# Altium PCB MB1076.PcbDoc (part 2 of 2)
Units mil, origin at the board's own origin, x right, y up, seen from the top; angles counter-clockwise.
Board outline 2200 x 4400 mil, 2 copper layers (TOP, Bottom), stack 60.433 mil thick; 144 components, 144 nets, 518 pads, 266 vias.
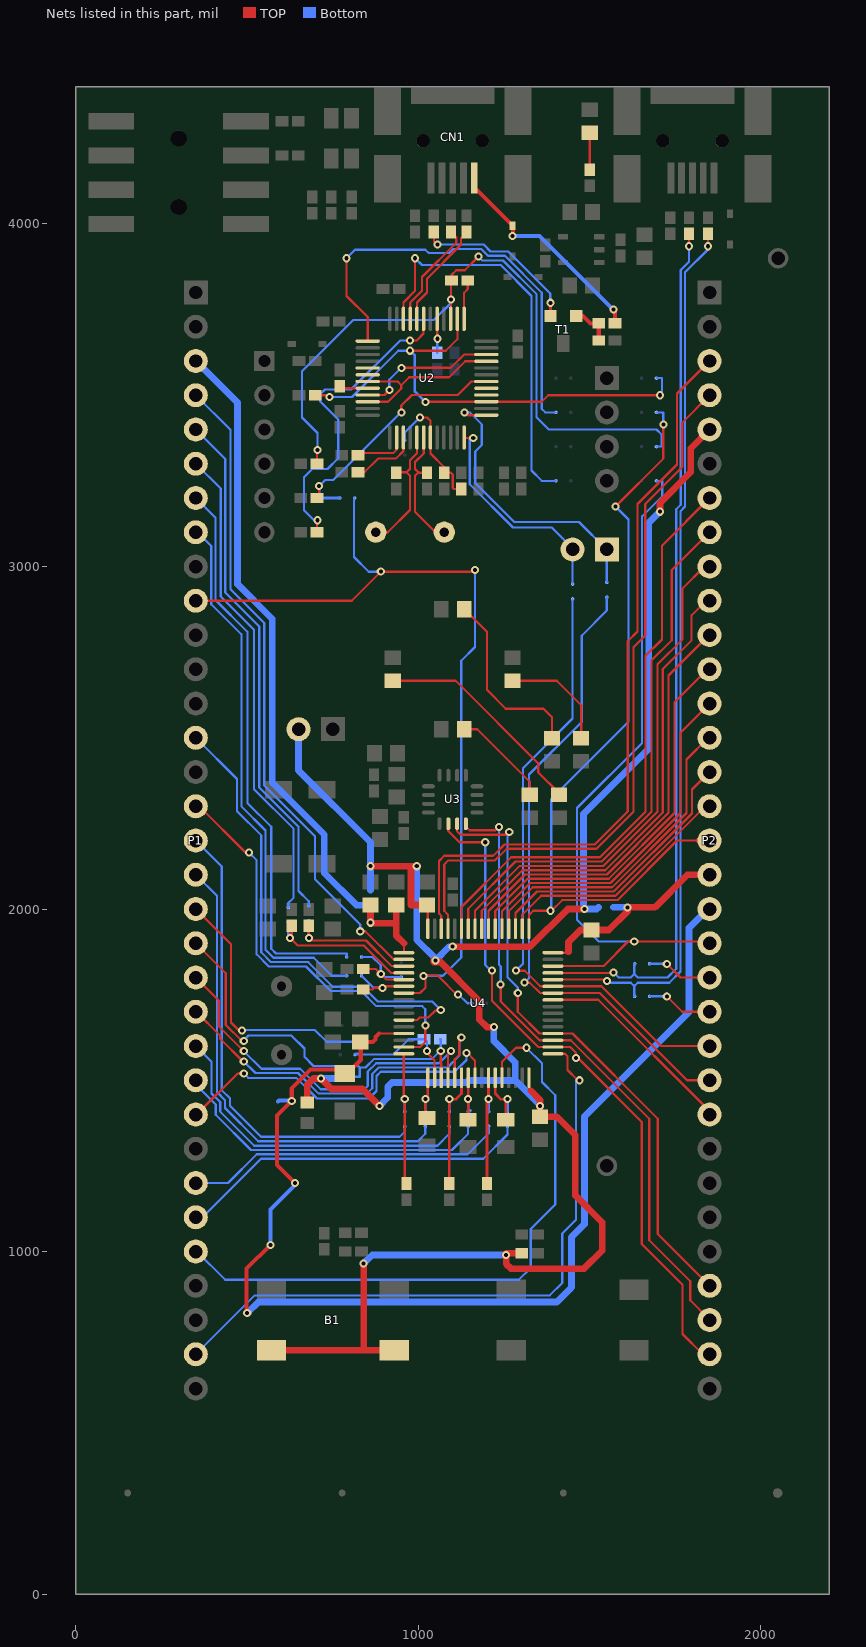
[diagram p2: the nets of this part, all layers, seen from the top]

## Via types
v1: diameter 23.62, hole 11.81, TOP to Bottom, 186 vias
v2: diameter 23.62, hole 11.81, TOP to Bottom, tented both sides, 80 vias

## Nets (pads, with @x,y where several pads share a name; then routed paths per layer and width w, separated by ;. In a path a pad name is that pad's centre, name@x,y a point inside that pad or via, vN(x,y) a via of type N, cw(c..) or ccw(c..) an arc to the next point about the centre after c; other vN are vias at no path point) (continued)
NetLD2_1: LD2.1 R3.1 | length 107.9
  TOP w6.5: R3.1@1500,4158.62 LD2.1@1500,4266.54
NetLD3_1: LD3.1 R29.2 | length 547.8
  TOP w6.5: LD3.1@1133.46,2875 1134.5,2875 1200,2809.5 1200,2640 1255,2585 1365,2585 1390,2560 R29.2@1390,2498.47
NetLD4_1: LD4.1 R32.2 | length 641.4
  TOP w6.5: LD4.1@925,2666.54 1108.46,2666.54 1350,2425 1350,2398.5 1410,2338.5 R32.2@1410,2333.47
NetLD5_1: LD5.1 R30.2 | length 326.2
  TOP w6.5: LD5.1@1275,2666.54 1403.46,2666.54 1475,2595 R30.2@1475,2498.47
NetLD6_1: LD6.1 R31.2 | length 293.2
  TOP w6.5: LD6.1@1133.46,2525 1171.5,2525 1325,2371.5 R31.2@1325,2333.47
NetR8_2: R8.2 T1.2 | length 498.1
  TOP w6.5: R8.2@1045,3976.38 1045,3948.72 1055,3938.72 v1(1055,3940)
  TOP w7.87: v1(1385,3770) 1385.33,3769.67 T1.2@1385.33,3731.34
  Bottom w6.5: v1(1055,3940) 1190.5,3940 1210.5,3920 1262,3920 1385,3797 v1(1385,3770)
NetR16_1: R16.1 R17.2 T1.1 | length 125.3
  TOP w11.81: T1.1@1460.33,3731.34 1480.16,3731.34 1502.5,3709 R16.1@1526.38,3709 ; R17.2@1526.38,3660 R16.1@1526.38,3709 ; R16.1@1526.38,3710 R16.1@1526.38,3709
NetR19_2: R19.2 U2.44 | length 84.2
  TOP w6.5: R19.2@770,3526.38 775.91,3520.47 U2.44@851.77,3520.47
NetR22_2: R22.2 U2.2 | length 158.5
  TOP w6.5: R22.2@823.62,3325 823.62,3331 926,3331 936.42,3341.42 U2.2@936.42,3376.77
NetR23_2: R23.2 U2.3 | length 197.9
  TOP w6.5: R23.2@823.62,3275 842,3275 882,3315 934,3315 956.1,3337.1 U2.3@956.1,3376.77
NetR44_1: R44.1 U2.29 | length 100.1
  TOP w6.5: U2.29@1054.53,3723.23 1054.53,3665 v1(1055,3665)
  Bottom w6.5: R44.1@1055,3623.62 v1(1055,3665)
NRST: P1.10 SB10.2 SB22.1 U4.7 | length 2685.7
  TOP w6.5: P1.10@350,2900 805,2900 v1(890,2985) 1160,2985 v1(1165,2990) ; U4.7@957.48,1754.53 1004.53,1754.53 1020.5,1770.5 1020.5,1805 v1@1020,1805 ; v1(1015,1805) v1@1020,1805 ; v1(1115,1750) 1115,1747 1056,1806 1020,1806 v1@1020,1805
  Bottom w6.5: SB10.2@813.62,3200 812,3200 812,3028 855,2985 v1(890,2985) ; v1(1015,1805) 1071.5,1805 1125,1858.5 1125,2725 1165,2765 v1(1165,2990) ; v1(1115,1750) 1118,1750 1143,1725 SB22.1@1155.32,1725
OSC_IN: C9.1 U2.5 X1.2 | length 385.6
  TOP w6.5: X1.2@875.36,3100.2 910.2,3100.2 975,3165 975,3265 965,3275 ; C9.1@935,3273.62 936.38,3275 965,3275 ; U2.5@995.47,3376.77 995.47,3330.47 975,3310 975,3285 965,3275
OSC_OUT: C10.1 U2.6 X1.1 | length 372
  TOP w6.5: U2.6@1015.16,3376.77 1015.16,3330.16 990,3305 990,3285 1001.38,3273.62 ; C10.1@1025,3273.62 1001.38,3273.62 ; X1.1@1075.36,3100.2 1049.8,3100.2 990,3160 990,3265 998.62,3273.62 1001.38,3273.62
PA1: P1.16 U4.15 | length 1240.7
  TOP w6.5: P1.16@350,2300 360,2300 495,2165 v1(505,2165) ; U4.15@957.48,1597.05 1005.55,1597.05 1020,1611.5 v1(1020,1660)
  Bottom w6.5: v1(505,2165) 527.5,2142.5 527.5,1868 563,1832.5 671.5,1832.5 743.5,1760.5 833,1760.5 877,1716.5 1011,1716.5 1020,1707.5 v1(1020,1660)
PA2: P1.17 SB27.1 | length 1385.2
  Bottom w6.5: P1.17@350,2200 426,2124 426,1471 449.5,1447.5 449.5,1425.5 540,1335 945,1335 960,1350 SB27.1@960,1365.32
PA3: P1.18 SB28.1 | length 1372.1
  Bottom w6.5: P1.18@350,2100 411.5,2038.5 411.5,1465.5 435,1442 435,1419 532,1322 998.5,1322 1020,1343.5 SB28.1@1020,1365.32
PA4: P1.21 U4.20 | length 1076.3
  TOP w6.5: P1.21@350,1800 417,1733 417,1658 v1(490,1585) ; U4.20@1086.42,1507.48 1086.42,1576.42 v1(1095,1585)
  Bottom w6.5: v1(490,1585) 541.5,1533.5 654.5,1533.5 714.5,1473.5 842.5,1473.5 852,1483 852,1525.5 876.5,1550 1060,1550 v1(1095,1585)
PA5: P1.22 U4.21 | length 1128.5
  TOP w6.5: P1.22@350,1700 350.75,1700.75 421.5,1630 421.5,1621 487.5,1555 v1(490,1555) ; U4.21@1106.1,1507.48 1106.1,1561.6 1119,1574.5 1119,1619 v1(1125,1625)
  Bottom w6.5: v1(490,1555) 524,1521 648.5,1521 708.5,1461 849,1461 865,1477 865,1518.5 884,1537.5 1084.5,1537.5 1119,1572 1119,1625 v1(1125,1625)
PA6: P1.23 SB29.1 | length 967.2
  Bottom w6.5: P1.23@350,1600 396,1554 396,1461.5 421,1436.5 421,1408.5 520.5,1309 1055.5,1309 1090,1343.5 SB29.1@1090,1365.32
PA7: P1.24 SB30.1 | length 945.5
  Bottom w6.5: P1.24@350,1500 350,1487.5 408,1429.5 408,1399.5 511,1296.5 1098,1296.5 1145,1343.5 SB30.1@1145,1365.32
PA8: P2.25 U4.41 | length 602.3
  TOP w6.5: U4.41@1392.52,1734.84 1525.16,1734.84 1849.5,1410.5 1849.5,1400 P2.25@1850,1400
PA9: P2.24 SB12.1 U4.42 | length 1882.8
  TOP w6.5: v1(1310,1785) 1325,1785 1355.47,1754.53 1529.47,1754.53 1784,1500 P2.24@1850,1500
  Bottom w6.5: v1(1310,1785) 1323,1798 1323,2392.5 1476.5,2546 1476.5,2798 1550,2871.5 SB12.1@1550,2910.32
PA10: P2.23 SB11.1 U4.43 | length 1809.8
  TOP w6.5: v1(1285,1820) 1310,1820 1355.79,1774.21 U4.43@1392.52,1774.21 1534.29,1774.21 1708.5,1600 P2.23@1850,1600
  Bottom w6.5: v1(1285,1820) 1305,1840 1305,2411 1450,2556 SB11.1@1450,2905.32
PA11: P2.22 SB23.1 | length 208.1
  TOP w6.5: v1(1725,1745) 1770,1700 P2.22@1850,1700
  Bottom w6.5: SB23.1@1674.68,1745 1715,1745 1725,1755 v1(1725,1745)
PA12: P2.21 SB20.1 | length 191.9
  TOP w6.5: v1(1725,1840) 1765,1800 P2.21@1850,1800
  Bottom w6.5: SB20.1@1674.68,1840 v1(1725,1840)
PA13: P2.20 SB9.1 U4.46 | length 2084.5
  TOP w6.5: U4.46@1392.52,1833.27 1540,1833.27 1611.73,1905 v1(1630,1905) 1845,1905 P2.20@1850,1900
  Bottom w6.5: v1(1630,1905) 1526.5,1905 1463,1968.5 1463,2295 1653,2485 1653,3146.5 1712,3205.5 1712,3250 SB9.1@1694.68,3250
PA14: P2.17 SB4.1 U4.49 | length 2301
  TOP w6.5: U4.49@1322.64,1942.52 1322.64,1982.64 1335,1995 v1(1385,1995) 1388.5,1995 1419.5,2026 1581,2026 1755,2200 P2.17@1820,2200 ; v1(1575,3175) 1715,3315 v1(1715,3415)
  TOP w19.68: P2.17@1820,2200 P2.17@1850,2200
  Bottom w6.5: v1(1385,1995) 1385,2004 1387.5,2006.5 1387.5,2321.5 1613,2547 1613,3137 v1(1575,3175) ; SB4.1@1694.68,3450 1715,3450 v1(1715,3415)
PA15: P2.16 U4.50 | length 718.8
  TOP w6.5: U4.50@1302.95,1942.52 1302.95,1982.95 1358.5,2038.5 1575.53,2038.5 1837.03,2300 P2.16@1850,2300
PB0: P1.27 SB31.1 | length 935.1
  Bottom w6.5: P1.27@350,1200 444,1200 528,1284 1143.5,1284 1205,1345.5 SB31.1@1205,1365.32
PB1: P1.28 SB32.1 | length 1033.6
  Bottom w6.5: P1.28@350,1100 369.5,1100 540.5,1271 1189,1271 1260,1342 SB32.1@1260,1365.32
PB2: P1.29 U4.28 | length 1868.3
  TOP w6.5: U4.28@1243.9,1507.48 1243.9,1553.9 1285,1595 v1(1315,1595)
  Bottom w6.5: P1.29@350,1000 353,1000 435.5,917.5 1293,917.5 1327.5,952 1327.5,1065.5 1399.5,1137.5 1399.5,1456 1360.5,1495 1360.5,1549.5 v1(1315,1595)
PB3: P2.11 U4.55 | length 1266.2
  TOP w6.5: U4.55@1204.53,1942.52 1204.53,1994.53 1311,2101 1550.31,2101 1730,2280.69 1730,2682 1848,2800 P2.11@1850,2800
PB4: P2.10 U4.56 | length 1380.5
  TOP w6.5: U4.56@1184.84,1942.52 1184.84,1994.84 1303.5,2113.5 1545.26,2113.5 1713.5,2281.74 1713.5,2701 1797.5,2785 1797.5,2857.5 1840,2900 P2.10@1850,2900
PB5: P2.9 U4.57 | length 1493
  TOP w6.5: U4.57@1165.16,1942.52 1165.16,1995.16 1296,2126 1540.22,2126 1697.5,2283.28 1697.5,2714 1770,2786.5 1770,2935 1835,3000 P2.9@1850,3000
PB6: P2.8 U4.58 | length 1596.7
  TOP w6.5: U4.58@1145.47,1942.52 1145.47,2000.47 1283.5,2138.5 1535.18,2138.5 1680,2283.32 1680,2725.5 1739.5,2785 1739.5,2989.5 P2.8@1850,3100
PB7: P2.7 U4.59 | length 1709.3
  TOP w6.5: U4.59@1125.79,1942.52 1125.79,2005.79 1271,2151 1530.13,2151 1662.5,2283.37 1662.5,2738.5 1711,2787 1711,3061 P2.7@1850,3200
PB8: P2.4 U4.61 | length 2117
  TOP w6.5: U4.61@1086.42,1942.52 1086.42,1983.58 1075,1995 1075,2130 1087,2142 1223.5,2142 1257.5,2176 1520.04,2176 1628,2283.96 1628,2764.5 1662,2798.5 1662,3182.5 1770,3290.5 1770,3420 P2.4@1850,3500
PB9: P2.3 U4.62 | length 2225.6
  TOP w6.5: U4.62@1066.73,1942.52 1066.73,1980 1060,1986.73 1060,2140 1075.5,2155.5 1218,2155.5 1251,2188.5 1515,2188.5 1611,2284.5 1611,2782 1639.5,2810.5 1639.5,3182.5 1755,3298 1755,3505 P2.3@1850,3600
PB12: P1.32 U4.33 | length 1907.4
  TOP w6.5: U4.33@1392.52,1577.36 1427.64,1577.36 1435,1570 1435,1530 1465,1500 v1(1470,1500)
  Bottom w6.5: P1.32@350,700 522,872 1383.5,872 1419.5,908 1419.5,1052.5 1460,1093 1460,1500 v1(1470,1500)
PB13: P2.32 U3.2 U4.34 | length 1980.5
  TOP w6.5: U3.2@1087.2,2249.13 1087.2,2227.8 1120,2195 v1(1195,2195) ; v1(1215,1820) 1215,1732.05 1350,1597.05 1442.95,1597.05 1460,1580 v1(1460,1565) 1465.5,1565 1652,1378.5 1652,1022 1771,903 1771,759 1830,700 P2.32@1850,700
  Bottom w6.5: v1(1195,2195) 1195,1836.5 1211.5,1820 v1(1215,1820)
PB14: P2.31 U3.4 U4.35 | length 1861.6
  TOP w6.5: U3.4@1138.39,2249.13 1138.39,2241.61 1150,2230 1225,2230 v1(1235,2240) ; v1(1240,1780) 1240,1730 1353.27,1616.73 U4.35@1392.52,1616.73 1445,1616.73 1674,1387.73 1674,1033 1793.5,913.5 1793.5,857.5 1850,801 P2.31@1850,800
  Bottom w6.5: v1(1235,2240) 1235,1837.5 1240,1832.5 v1(1240,1780)
PB15: P2.30 U3.3 U4.36 | length 1812.5
  TOP w6.5: U3.3@1112.8,2249.13 1112.8,2227.2 1123,2217 1257,2217 v1(1265,2225) ; v1(1290,1755) 1290,1700 1353.58,1636.42 1450,1636.42 1698.5,1387.92 1698.5,1051.5 P2.30@1850,900
  Bottom w6.5: v1(1265,2225) 1260,2225 1260,1801 1290,1771 v1(1290,1755)
PC3: P1.14 U4.11 | length 1421
  TOP w6.5: U4.11@957.48,1675.79 996.79,1675.79 1004,1683 1028.5,1683 1049.5,1704 1066,1704 v1(1065,1705)
  Bottom w6.5: P1.14@350,2500 470.5,2379.5 470.5,2285.5 541,2215 541,1873.5 569.5,1845 678,1845 750,1773 838.5,1773 881.5,1730 1040,1730 v1(1065,1705)
PC4: P1.25 U4.24 | length 1047.3
  TOP w6.5: P1.25@350,1400 352,1400 472,1520 v1(490,1520) ; v1(1140,1580) 1142.5,1580 1165.16,1557.34 U4.24@1165.16,1507.48
  Bottom w6.5: v1(490,1520) 503,1507 643.5,1507 704,1446.5 855,1446.5 877.5,1469 877.5,1512.5 890,1525 1105.5,1525 1140,1559.5 v1(1140,1580)
PC10: P2.15 U4.51 | length 824
  TOP w6.5: U4.51@1283.27,1942.52 1283.27,1988.27 1346,2051 1570.49,2051 1798.5,2279.01 1798.5,2349 1849.5,2400 P2.15@1850,2400
PC11: P2.14 U4.52 | length 938.6
  TOP w6.5: U4.52@1263.58,1942.52 1263.58,1993.58 1333.5,2063.5 1565.44,2063.5 1782.5,2280.56 1782.5,2436.5 1846,2500 P2.14@1850,2500
PC12: P2.13 U4.53 | length 1045.8
  TOP w6.5: U4.53@1243.9,1942.52 1243.9,1993.9 1326,2076 1560.4,2076 1765,2280.6 1765,2514.5 1850,2599.5 P2.13@1850,2600
PC13: P1.4 U4.2 | length 1925.3
  TOP w6.5: v1(830,1935) 845,1935 927.05,1852.95 U4.2@957.48,1852.95
  Bottom w6.5: P1.4@350,3500 451,3399 451,2934 550,2835 550,2360.5 698,2212.5 698,2087 830,1955 v1(830,1935)
PC14: P1.5 SB14.1 | length 1527
  Bottom w6.5: P1.5@350,3400 436,3314 436,2924 535,2825 535,2355 650,2240 650,2052.5 680,2022.5 SB14.1@680,2009.68
PC14-OSC32_IN: R35.1 SB14.2 U4.3 | length 403.2
  TOP w6.5: R35.1@680,1951.38 v1(680,1915) 680,1908 847,1908 921.73,1833.27 U4.3@957.48,1833.27
  Bottom w6.5: v1(680,1915) SB14.2@680,1966.38
PC15: P1.6 SB13.1 | length 1420
  Bottom w6.5: P1.6@350,3300 422.5,3227.5 422.5,2912.5 520,2815 520,2350 635.5,2234.5 635.5,2033 620,2017.5 SB13.1@620,2004.68
PC15-OSC32_OUT: R34.1 SB13.2 U4.4 | length 474.7
  TOP w6.5: v1(625,1915) v1@625,1916 ; R34.1@630,1951.38 630,1923.72 625,1928.72 v1@625,1916 ; U4.4@957.48,1813.58 920,1813.58 840.08,1893.5 647.5,1893.5 v1@625,1916
  Bottom w6.5: SB13.2@620,1961.38 620,1915 v1(625,1915)
PD2: P2.12 U4.54 | length 1158.9
  TOP w6.5: U4.54@1224.21,1942.52 1224.21,1994.21 1318.5,2088.5 1555.35,2088.5 1747.5,2280.65 1747.5,2603.5 1844,2700 P2.12@1850,2700
PF0: P1.7 SB17.1 | length 1643.2
  Bottom w6.5: P1.7@350,3200 407.5,3142.5 407.5,2902.5 500.5,2809.5 500.5,2309.5 570,2240 570,1884 584,1870 790.31,1870 SB17.1@790.32,1860
PF0-OSC_IN: R36.1 SB17.2 SB19.2 U4.5 | length 287.6
  TOP w6.5: R36.1@838.62,1825 875,1825 v1(890,1810) 906.1,1793.9 U4.5@957.48,1793.9
  Bottom w6.5: SB17.2@833.62,1860 866,1860 890,1836 v1(890,1810) 898.62,1801.38 SB19.2@950,1801.38
PF1: P1.8 SB18.1 | length 1574.5
  Bottom w6.5: P1.8@350,3100 355,3100 395,3060 395,2890 483,2802 483,2300 553.5,2229.5 553.5,1881 577,1857.5 694,1857.5 746.5,1805 SB18.1@790.32,1805
PF1-OSC_OUT: R37.1 SB18.2 U4.6 | length 198.5
  TOP w6.5: R37.1@838.62,1765 866.28,1765 871.28,1770 v1(895,1770) 899.21,1774.21 U4.6@957.48,1774.21
  Bottom w6.5: SB18.2@833.62,1805 868.62,1770 v1(895,1770)
STLINK_RX: JP1.1 SB12.2 U2.13 | length 870.8
  TOP w6.5: v1(1135,3450) 1143.27,3441.73 U2.13@1198.23,3441.73
  Bottom w6.5: v1(1135,3450) 1150,3450 1185,3415 1185,3354.5 1166,3335.5 1166,3244 1280,3130 1468.5,3130 1548.5,3050 JP1.1@1550,3050 SB12.2@1550,2953.62
STLINK_TX: JP1.2 SB11.2 U2.12 | length 655.6
  TOP w6.5: U2.12@1133.27,3376.77 1133.27,3375 v1(1160,3375)
  Bottom w6.5: v1(1160,3375) 1150,3375 1150,3240 1276,3114 1389.5,3114 1450,3053.5 JP1.2@1450,3050 SB11.2@1450,2948.62
STM_JTCK: SB3.2 U2.37 | length 1294.6
  TOP w6.5: v1(790,3900) 790,3790 851.77,3728.23 U2.37@851.77,3658.27
  Bottom w6.5: v1(790,3900) 815,3925 1020,3925 1030,3915 1090,3915 1102,3927 1183,3927 1203,3907 1252.5,3907 1360,3799.5 1360,3460 1370,3450 SB3.2@1401.38,3450
STM_JTMS: SB8.2 U2.34 | length 1170.2
  TOP w6.5: U2.34@956.1,3723.23 956.1,3771.1 990,3805 v1(990,3900)
  Bottom w6.5: v1(990,3900) 1010,3880 1240,3880 1330,3790 1330,3280 1360,3250 SB8.2@1401.38,3250
STM_RST: C11.2 R25.1 SB5.2 U2.7 | length 380.2
  TOP w6.5: v1(1005,3435) 1025,3435 1034.84,3425.16 U2.7@1034.84,3376.77 1034.84,3330 1075,3289.84 C11.2@1075,3273.62 1095,3273.62 1100,3268.62 1100,3230 1103.62,3226.38 R25.1@1125,3226.38
  Bottom w6.5: SB5.2@960,3368.62 960,3391.5 1003.5,3435 v1(1005,3435)
SWIM: U2.22 U2.45 | length 413
  TOP w6.5: U2.45@851.77,3500.79 900.79,3500.79 v1(915,3515) ; v1(950,3580) 1094.5,3580 1133.4,3618.9 U2.22@1198.23,3618.9
  Bottom w6.5: v1(915,3515) 915,3545 v1(950,3580)
SWIM_IN: U2.21 U2.43 U2.46 | length 503.6
  TOP w6.5: U2.46@851.77,3481.1 911.1,3481.1 950,3520 950,3529.5 ; U2.43@851.77,3540.16 939.34,3540.16 950,3529.5 ; U2.21@1198.23,3599.21 1136.21,3599.21 1089.5,3552.5 973,3552.5 950,3529.5
SWIM_RST: U2.42
SWIM_RST_IN: U2.41
T_JTCK: R20.2 SB2.1 U2.15 U2.26 | length 1481.4
  TOP w6.5: R20.2@698.62,3500 735,3500 v1(740,3495) ; v1(975,3630) 1080,3630 1113.58,3663.58 U2.26@1113.58,3723.23 ; v1(1020,3480) 1020,3481.1 U2.15@1198.23,3481.1 1360.1,3481.1 1379,3500 v1(1705,3500)
  Bottom w6.5: v1(740,3495) 806,3495 941,3630 v1(975,3630) ; SB2.1@1694.68,3550 1711,3550 1711,3500 v1(1705,3500)
  Bottom w7.87: v1(975,3630) 989.5,3615.5 989.5,3510.5 v1(1020,3480)
T_JTDI: U2.17
T_JTDO: U2.16
T_JTMS: R14.2 R21.2 SB7.1 U2.27 | length 2060.4
  TOP w6.5: R21.2@703.62,3300 703.62,3338.62 v1(705,3340) ; U2.27@1093.9,3723.23 1095,3723.23 v1(1095,3780) 1095,3835 R14.2@1096.38,3835 1096.38,3851.38 1110,3865 1135,3865 v1(1175,3905)
  Bottom w6.5: v1(705,3340) 705,3390 660,3435 660,3570 809.5,3719.5 1045,3719.5 1095,3769.5 v1(1095,3780) ; v1(1175,3905) 1186.5,3893.5 1246.5,3893.5 1345,3795 1345,3435 1380,3400 1695,3400 1710,3385 1710,3350 SB7.1@1694.68,3350
T_NRST: R24.2 SB10.1 U2.18 | length 758.1
  TOP w6.5: R24.2@703.62,3200 710,3200 v1(710,3235) ; v1(950,3450) 950,3470 981,3501 1115,3501 1154.16,3540.16 U2.18@1198.23,3540.16
  Bottom w6.5: v1(710,3235) 727.5,3252.5 751.5,3252.5 949,3450 v1(950,3450)
  Bottom w7.87: v1(710,3235) 710,3208.5 718.5,3200 SB10.1@770.32,3200
T_SWDIO_IN: R14.1 U2.25 | length 116.1
  TOP w6.5: U2.25@1133.27,3723.23 1133.27,3799.65 1143.62,3810 R14.1@1143.62,3835
T_SWO: R28.2 U2.31 | length 933.8
  TOP w6.5: R28.2@703.62,3100 703.62,3135 v1(705,3135) ; v1(975,3660) 995,3660 1015,3680 1015,3723.23 U2.31@1015.16,3723.23
  Bottom w6.5: v1(705,3135) 695,3135 665.5,3164.5 665.5,3260.5 690,3285 734.5,3285 765.5,3316 765.5,3429.5 713.5,3481.5 713.5,3503 727,3516.5 803,3516.5 946.5,3660 v1(975,3660)
TS_G1_IO3: R38.1 SB27.2 U4.16 | length 422.2
  TOP w7.87: U4.16@957.48,1577.36 957.48,1446.52 v1@960,1444 ; v1(960,1445) v1@960,1444 ; R38.1@965,1198.62 960,1198.62 v1@960,1444
  Bottom w7.87: SB27.2@960,1408.62 v1(960,1445)
TS_G1_IO4: C26.2 SB28.2 U4.17 | length 161.9
  TOP w7.87: C26.2@1025,1390 1020,1390 v1(1020,1445) 1020,1447.5 1027.36,1454.86 U4.17@1027.36,1507.48
  Bottom w7.87: SB28.2@1020,1408.62 v1(1020,1445)
TS_G2_IO3: R39.1 SB29.2 U4.22 | length 371.8
  TOP w7.87: R39.1@1090,1198.62 v1(1090,1445) 1110,1445 1125.79,1460.79 U4.22@1125.79,1507.48
  Bottom w7.87: SB29.2@1090,1408.62 v1(1090,1445)
TS_G2_IO4: C27.2 SB30.2 U4.23 | length 174.5
  TOP w7.87: C27.2@1145,1385 1145.47,1394.53 1145.47,1438.5 1145,1438.03 v1@1145,1443 ; v1(1145,1445) v1@1145,1443 ; U4.23@1145.47,1507.48 1145.47,1443.47 v1@1145,1443
  Bottom w7.87: SB30.2@1145,1408.62 1149.12,1408.62 1152,1411.5 1145,1411.5 v1(1145,1445)
TS_G3_IO2: R40.1 SB31.2 U4.26 | length 356.2
  TOP w7.87: R40.1@1200,1198.62 v1@1200,1437.97 ; U4.26@1204.53,1507.48 v1@1204.53,1444.53 ; v1(1205,1445) v1@1204.53,1444.53 ; v1@1200,1437.97 1204.53,1442.5 v1@1204.53,1444.53 ; v1@1200,1437.97 1200,1440 v1@1204.53,1444.53
  Bottom w7.87: SB31.2@1205,1408.62 v1(1205,1445)
TS_G3_IO3: C28.2 SB32.2 U4.27 | length 185.4
  TOP w7.87: U4.27@1224.21,1507.48 1224.21,1460.79 1240,1445 v1@1255,1445 ; C28.2@1255,1385 v1@1255,1445 ; v1(1260,1445) v1@1255,1445
  Bottom w7.87: SB32.2@1260,1408.62 v1(1260,1445)
U5V: CN1.1 D1.1 R16.2 | length 645.4
  TOP w11.81: CN1.1@1162.89,4134.25 1162.89,4107.11 D1.1@1275,3995 1276,3995 1276,3965 v1(1275,3965) ; v1(1570,3750) 1573.62,3750 R16.2@1573.62,3710
  Bottom w11.81: v1(1275,3965) 1353.5,3965 1568.5,3750 v1(1570,3750)
USB_DM: R10.2 U2.32 | length 313
  TOP w6.55: U2.32@995.47,3723.23 995.47,3770.47 1025,3800 1025,3840.5 1124.5,3940 1124.5,3957.5 1140,3973 R10.2@1140,3976.38
USB_DP: R9.2 U2.33 | length 315
  TOP w6.55: U2.33@975.79,3723.23 975.79,3770.79 1010,3805 1010,3845.5 1110,3945.5 1110,3961.38 R9.2@1095,3976.38
USBF4_DM: R13.2 SB23.2 U4.44 | length 2619.2
  TOP w6.55: U4.44@1392.52,1793.9 1546.1,1793.9 v1(1550,1790) ; v1(1845,3935) R13.2@1845,3971.38
  Bottom w6.55: v1(1550,1790) 1550,1785 1620,1785 1630,1775 ; SB23.2@1631.38,1745 1630,1745 1630,1775 ; v1(1845,3935) 1845,3925.5 1778.5,3859 1778.5,3175 1765,3161.5 1765,1817.5 1732.5,1785 1640,1785 1630,1775
USBF4_DP: R12.2 SB20.2 U4.45 | length 2591.6
  TOP w6.55: U4.45@1392.52,1813.58 1570,1813.58 v1(1570,1815) ; v1(1790,3935) 1798.72,3935 1794.36,3939.36 1790,3943.72 R12.2@1790,3971.38
  Bottom w6.55: v1(1570,1815) 1585,1800 1620,1800 1630,1810 ; SB20.2@1631.38,1840 1630,1840 1630,1810 ; v1(1790,3935) 1790,3890 1765.5,3865.5 1765.5,3180.5 1752.5,3167.5 1752.5,1825.5 1727,1800 1640,1800 1630,1810
VBAT: C16.1 C17.2 P1.3 SB15.2 U4.1 | length 2151.7
  TOP w6.5: C16.1@860,2010 C16.1@860,2011.53 ; U4.1@957.48,1872.64 957.48,1900
  TOP w19.68: C16.1@860,2010 v1(860,1960) 860,1958.5 935,1958.5 ; C17.2@935,2011.53 935,1958.5 ; 957.48,1900 935,1922.48 935,1958.5
  Bottom w19.68: P1.3@350,3600 471.5,3478.5 471.5,2948.5 573,2847 573,2369 725,2217 725,2105 818.62,2011.38 SB15.2@860,2011.38 v1(860,1960)
VDD: B1.1 B1.4 C18.1 C29.2 JP2.2 L1.1 P2.5 R43.2 SB15.1 SB16.1 SB25.2 U4.32 U4.64 | length 6755.5
  TOP w6.5: C18.1@1025,2011.53 1027.36,2009.17 U4.64@1027.36,1942.52 ; U4.32@1322.64,1507.48 1322.64,1475 1328.14,1469.5
  TOP w19.68: B1.4@570.87,711.42 841,711.42 ; L1.1@675,1435 675,1486.5 693.5,1505 v1(715,1505) 745.5,1474.5 836.5,1474.5 v1(886,1425) ; v1(840,965) 840,712.42 841,711.42 ; v1(860,2125) 978,2125 ; B1.1@929.13,711.42 841,711.42 ; v1(995,2125) 978,2125 ; C18.1@1025,2011.53 978,2011.54 978,2125 ; v1(1050,1850) 1045,1850 1045,1845 1064,1845 1177.5,1731.5 1177.5,1677 1199.5,1655 v1(1220,1655) ; v1(1100,1890) 1326,1890 1436,2000 v1(1485,2000) ; v1(1255,990) 1252,990 v1@1256,994 ; R43.2@1301.38,995 1256,995 v1@1256,994 ; 1328.14,1469.5 1355,1442.64 v1(1355,1425) C29.2@1355,1393.47 1404.03,1393.47 1458,1339.5 1458,1163 1536.5,1084.5 1536.5,1003 1483.5,950 1270,950 1256,964 v1@1256,994 ; v1(1705,3160) 1705,3185.5 1795,3275.5 1795,3345 P2.5@1850,3400
  Bottom w19.68: JP2.2@650,2525 650,2405 860,2195 v1(860,2125) SB15.1@860,2054.68 ; v1(715,1505) 760,1505 765.69,1510.69 SB25.2@766.38,1510 ; v1(840,965) 865,990 v1(1255,990) ; v1(886,1425) 910,1449 910,1480.5 923,1493.5 1140.5,1493.5 1146,1499 1279.5,1499 ; v1(995,2125) 995,1910 1050,1855 v1(1050,1850) 1090,1890 v1(1100,1890) ; v1(1220,1655) 1220,1614.5 1282.5,1552 1282.5,1502 1279.5,1499 ; v1(1355,1425) 1355,1427.5 1283.5,1499 1279.5,1499 ; SB16.1@1525.32,2005 1520.31,2000 v1(1485,2000) 1482,2000 1482,2278 1672.5,2468.5 1672.5,3128 1705,3160.5 v1(1705,3160)
VDD3: C33.1 P1.20 SB25.1 U4.19 | length 1163.6
  TOP w6.5: P1.20@350,1900 437.5,1812.5 437.5,1661.5 484,1615 v1(490,1615) ; v1(1065,1585) 1065,1550 1066.73,1548.27 U4.19@1066.73,1507.48
  Bottom w6.5: v1(490,1615) 490,1617 504,1631 628.5,1631 667,1592.5 667,1568.5 693.5,1542 823.5,1542 828.5,1537 ; SB25.1@809.68,1510 828.5,1510 828.5,1537 ; C33.1@1063.62,1620 1065,1620 v1@1065,1587.5 ; v1(1065,1585) v1@1065,1587.5 ; 828.5,1537 845.5,1537 871,1562.5 1040,1562.5 v1@1065,1587.5
VDD_USB: C21.2 P2.18 SB16.2 U4.48 | length 616.4
  TOP w7.87: U4.48@1392.52,1872.64 1435,1872.64 1437.86,1875.5
  TOP w19.68: 1437.86,1875.5 1438,1875.64 1438,1903.5 1472.96,1938.47 C21.2@1505,1938.47 1555.46,1938.47 1610,1993 v1(1610,2005) 1690,2005 1785,2100 P2.18@1850,2100
  Bottom w19.68: SB16.2@1568.62,2005 v1(1610,2005)
VDDA: C24.2 C25.1 P2.19 SB26.2 U4.13 | length 3510
  TOP w6.5: 885,1636.42 U4.13@957.48,1636.42
  TOP w11.81: v1(500,820) 505.5,820 498.5,827 498.5,950 v1(568,1019.5) ; v1(640,1200) 640,1200.5 587.5,1253 587.5,1397.5 v1(630,1440) 630,1476 685,1531 785,1531 C25.1@785,1520 792,1520 831.5,1559.5 C24.2@831.5,1611.54 ; C24.2@831,1611.54 C24.2@831.5,1611.54 ; 885,1636.42 884.42,1636.42 874.5,1626.5 874.5,1619.54 866.5,1611.54 C24.2@831.5,1611.54
  TOP w19.68: C24.2@830,1611.53 C24.2@831,1611.54
  Bottom w11.81: v1(568,1019.5) 568,1123 645,1200 v1(640,1200) ; SB26.2@590,1438.62 592.88,1441.5 630,1441.5 v1(630,1440)
  Bottom w19.68: v1(500,820) 533,853 1404,853 1446.5,895.5 1446.5,1042 1484.5,1080 1484.5,1394 1790,1699.5 1790,1945 1845,2000 P2.19@1850,2000
VSS3: C33.2 P1.19 SB24.1 U4.18 | length 1185.5
  TOP w6.5: P1.19@350,2000 452.5,1897.5 452.5,1669 479,1642.5 485,1642.5 v1(485,1645) ; v1(1025,1585) 1020.5,1585 1047.05,1558.45 U4.18@1047.05,1507.48
  Bottom w6.5: v1(485,1645) 487,1647 697.5,1647 732,1612.5 821.5,1612.5 834.5,1599.5 834.5,1577.5 817.18,1577.5 SB24.1@814.68,1575 926.5,1575 971.5,1620 C33.2@1016.38,1620 1018.5,1620 1025,1613.5 v1(1025,1585)
pads on no net: CN1.11 CN1.12 CN2.11 CN2.12 CN3.2 CN3.6 CN3.9 CN3.10 U2.4 U2.11 U2.14 U2.19 U2.28 U2.38 U2.39 U2.40 X2.2 X2.3

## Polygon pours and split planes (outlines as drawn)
GND on Bottom "BOTTOM_GND_P015" (hatched 90Degree grid 62.99 track 7.87, remove dead copper, pour order 15): -395,-305 2700,-305 2700,800 -395,800
GND on Bottom "BOTTOM_GND_P016" (solid, remove dead copper, pour order 16): -400,787 2695,787 2695,4470 -400,4470
GND on TOP "TOP_GND_P013" (hatched 90Degree grid 62.99 track 7.87, remove dead copper, pour order 13): 975,650 -449.43,650 -449.43,-465 2430,-465 2430,650 1225,650 1225,595 1472.86,595 1512.86,560 2105,560 cw(c2105,510) 2155,510 2155,85 cw(c2105,85) 2105,35 95,35 cw(c95,85) 45,85 45,510 cw(c95,510) 95,560 685,560 726.45,600 975,600
GND on TOP "TOP_GND_P014" (solid, remove dead copper, pour order 14): -422.93,600 975,600 975,975 900,1050 900,1585 995,1585 1016.5,1563.5 1301,1563.5 1301,1289 1278.5,1266.5 1278.5,1112 1225.5,1059 1225.5,595 2430,595 2430,4504.06 -422.93,4504.06

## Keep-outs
TOP:
  rectangle: 1547.24,3938.98 1551.42,3946.13
  rectangle: 1547.24,3903.87 1551.42,3909.45
  rectangle: 958.27,3199.61 964.57,3202.76
  rectangle: 1250,2196.85 1251.97,2206.69
  rectangle: 1269.68,2196.85 1271.65,2206.69
  rectangle: 1320.87,926.77 1321.65,933.07
  rectangle: 1269.68,925.2 1271.65,933.07
  region: 956.69,3562.99 964.57,3557.09 964.57,3562.99
  region: 1787.4,2862.2 1781.5,2864.17 1781.5,2860.24 1787.4,2860.24
  region: 1728.35,2992.13 1722.44,2994.09 1722.44,2990.16 1728.35,2990.16
  region: 1364.17,2204.72 1364.17,2198.82 1366.14,2198.82 1366.14,2204.72
  region: 1409.45,2204.72 1409.45,2198.82 1411.42,2198.82 1411.42,2204.72
Bottom:
  rectangle: 1405.31,3321.76 1448.82,3330.31
  rectangle: 1405.31,3369.69 1448.82,3378.24
  region: 1397.58,3369.69 1375.79,3369.68 1375.67,3353.9 1369.37,3353.9 1369.4,3369.68 1371.93,3375.79 1377.96,3378.3 1397.69,3378.24
  region: 1397.59,3330.31 1375.79,3330.32 1375.67,3346.1 1369.37,3346.1 1369.4,3330.32 1372.18,3323.6 1376.75,3321.7 1397.7,3321.76
  region: 979.68,3364.68 979.68,3295.79 961.3,3295.65 955.04,3289.4 979.68,3289.4 984.2,3291.27 988.21,3300.93 988.03,3364.79
  region: 940.32,3364.68 940.31,3295.79 950.08,3295.72 943.76,3289.4 940.31,3289.4 935.8,3291.27 931.63,3301.31 931.81,3364.8
  region: 814.68,1555.31 745.79,1555.32 745.67,1571.1 739.37,1571.1 739.4,1555.32 741.27,1550.8 745.79,1548.92 814.77,1549.11
  region: 814.68,1594.68 745.79,1594.68 745.67,1578.9 739.37,1578.9 739.4,1594.68 741.27,1599.2 745.79,1601.08 814.77,1600.89
Keep-Out Layer:
  the board outline again, w10

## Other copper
TOP:
  text "TOP LAYER" at -986.61,-3501.57 h96.46
Bottom:
  region net GND: 407.61,824.93 427.17,844.49 458.66,844.49 439.11,824.93
  text "BOTTOM LAYER" at -986.61,-3501.57 h96.46

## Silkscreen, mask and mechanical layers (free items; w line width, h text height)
Top Silk:
  drawing of 241 lines, arcs and shapes, not listed
  text "PWR" at 1427.17,4192.91 h78.74
  text "COM" at 710,4108.78 h78.74
  text "USB USER" at 2104.33,4100.39 h78.74 r90
  text "USB ST-LINK" at 1398.47,4056 h78.74 r90
  text "3V" at 150,3784.25 h78.74
  text "5V" at 1925,3784.25 h78.74
  text "GND" at 150,3684.25 h78.74
  text "GND" at 1925,3684.25 h78.74
  text "VBAT" at 150,3584.25 h78.74
  text "PB9" at 1925,3584.25 h78.74
  text "PC13" at 150,3484.25 h78.74
  text "PB8" at 1925,3484.25 h78.74
  text "PC14" at 150,3384.25 h78.74
  text "VDD" at 1925,3384.25 h78.74
  text "ST-LINK" at 1390,3366.14 h78.74 r90
  text "SWD" at 480.32,3291.34 h78.74 r90
  text "PC15" at 150,3284.25 h78.74
  text "BOOT0" at 1925,3284.25 h78.74
  text "DISCOVERY" at 1775,3275 h78.74 r90
  text "PF0" at 150,3184.25 h78.74
  text "PB7" at 1925,3184.25 h78.74
  text "TX" at 1420,3120.08 h59.06
  text "RX" at 1515.75,3120.08 h59.06
  text "PF1" at 150,3084.25 h78.74
  text "PB6" at 1925,3084.25 h78.74
  text "GND" at 150,2984.25 h78.74
  text "PB5" at 1925,2984.25 h78.74
  text "www.st.com/stm32f0-discovery" at 505.91,2929.13 h110.24
  text "NRST" at 150,2884.25 h78.74
  text "PB4" at 1925,2884.25 h78.74
  text "PC0" at 150,2784.25 h78.74
  text "PB3" at 1925,2784.25 h78.74
  text "PC1" at 150,2684.25 h78.74
  text "PD2" at 1925,2684.25 h78.74
  text "J" at 474.41,2639.76 h472.44
  text "ldd" at 665,2600.79 h59.06
  text "PC2" at 150,2584.25 h78.74
  text "PC12" at 1925,2584.25 h78.74
  text "PC3" at 150,2484.25 h78.74
  text "PC11" at 1925,2484.25 h78.74
  text "PA0" at 150,2384.25 h78.74
  text "PC10" at 1925,2384.25 h78.74
  text "PA1" at 150,2284.25 h78.74
  text "PA15" at 1925,2284.25 h78.74
  text "PA2" at 150,2184.25 h78.74
  text "PA14" at 1925,2184.25 h78.74
  text "STM32F072B-DISCO" at 1057.09,2122.05 h102.36
  text "PA3" at 150,2084.25 h78.74
  text "VDDIO2" at 1925,2084.25 h78.74
  text "VDDA" at 1925,1984.25 h78.74
  text "GND" at 155.12,1974.8 h78.74
  text "PA13" at 1925,1884.25 h78.74
  text "VDD" at 155.12,1876.38 h78.74
  text "PA4" at 150,1784.25 h78.74
  text "PA12" at 1925,1784.25 h78.74
  text "PA5" at 150,1684.25 h78.74
  text "PA11" at 1925,1684.25 h78.74
  text "PA6" at 150,1584.25 h78.74
  text "PA10" at 1925,1584.25 h78.74
  text "PA7" at 150,1484.25 h78.74
  text "PA9" at 1925,1484.25 h78.74
  text "MB1076D" at 1417.32,1417.32 h102.36
  text "PC4" at 150,1384.25 h78.74
  text "PA8" at 1925,1384.25 h78.74
  text "PC5" at 150,1284.25 h78.74
  text "PC9" at 1925,1284.25 h78.74
  text "PB0" at 150,1184.25 h78.74
  text "PC8" at 1925,1184.25 h78.74
  text "GND" at 1500,1125 h59.06
  text "PB1" at 150,1084.25 h78.74
  text "PC7" at 1925,1084.25 h78.74
  text "PB2" at 150,984.25 h78.74
  text "PC6" at 1925,984.25 h78.74
  text "PB10" at 147.64,885.83 h78.74
  text "PB15" at 1925,884.25 h78.74
  text "PB11" at 147.64,797.24 h78.74
  text "PB14" at 1925,784.25 h78.74
  text "PB12" at 147.64,688.98 h78.74
  text "PB13" at 1925,684.25 h78.74
  text "GND" at 1925,584.25 h78.74
  text "GND" at 147.64,580.71 h78.74
  text "USER" at 660,580 h59.06
  text "RESET" at 1375,575 h59.06
  text "SILKSCREEN TOP LAYER" at -986.61,-3501.57 h96.46
Bottom Overlay:
  region: 779.13,2587.4 cw(c779.13,2595.28) 779.13,2603.15 cw(c779.13,2595.28)
  region: 475.98,3595.28 cw(c475.98,3603.15) 475.98,3611.02 cw(c475.98,3603.15)
  region: 450,3805.32 cw(c450,3825) 450,3844.69 cw(c450,3825)
  region: 1515.35,3611.02 cw(c1515.35,3618.9) 1515.35,3626.77 cw(c1515.35,3618.9)
  region: 1594.09,3111.02 cw(c1594.09,3118.9) 1594.09,3126.77 cw(c1594.09,3118.9)
  region: 1750,3780.32 cw(c1750,3800) 1750,3819.69 cw(c1750,3800)
  lines w7.87: 1601.38,3799.57 617.13,3799.57 617.13,4153.9 1601.38,4153.9 1601.38,3800.79
  lines w8: 1350,3210 1500,3210 1500,3630 1350,3630 1350,3210 ; 1600,3210 1750,3210 1750,3630 1600,3630 1600,3210
  text "SN" at 1163.39,3978.35 h41.34
  text "3V" at 269.45,3774.02 h78.74
  text "5V" at 2006.92,3766.54 h78.74
  text "GND" at 269.45,3674.02 h78.74
  text "CN4" at 580.71,3671.26 h47.24
  text "GND" at 2045.3,3666.54 h78.74
  text "CN5" at 1586.68,3642.52 h47.24
  text "VBAT" at 269.45,3574.02 h78.74
  text "PB9" at 2027.45,3566.54 h78.74
  text "PC13" at 269.45,3474.02 h78.74
  text "PB8" at 2027.94,3466.54 h78.74
  text "PC14" at 269.45,3374.02 h78.74
  text "VDD" at 2042.13,3366.54 h78.74
  text "DEFAULT" at 1755,3356.65 h78.74 r270
  text "RESERVED" at 1297.24,3338.58 h78.74 r270
  text "PC15" at 269.45,3274.02 h78.74
  text "BOOT0" at 2090.84,3266.54 h78.74
  text "PF0" at 269.45,3174.02 h78.74
  text "PB7" at 2027.72,3166.54 h78.74
  text "JP1" at 1528.57,3111.02 h47.24
  text "PF1" at 269.45,3074.02 h78.74
  text "PB6" at 2027.99,3066.54 h78.74
  text "GND" at 269.45,2974.02 h78.74
  text "PB5" at 2027.12,2966.54 h78.74
  text "NRST" at 269.45,2874.02 h78.74
  text "PB4" at 2028.54,2866.54 h78.74
  text "PC0" at 269.45,2774.02 h78.74
  text "PB3" at 2027.01,2766.54 h78.74
  text "E" at 1543.31,2675.2 h275.59
  text "PC1" at 269.45,2674.02 h78.74
  text "PD2" at 2030.67,2666.54 h78.74
  text "K" at 1165,2655.51 h275.59
  text "JP2" at 718.5,2608.27 h47.24
  text "PC2" at 269.45,2574.02 h78.74
  text "PC12" at 2051.25,2566.54 h78.74
  text "PC3" at 269.45,2474.02 h78.74
  text "PC11" at 2051.36,2466.54 h78.74
  text "F" at 1160,2437.01 h275.59
  text "G" at 1557.09,2417.32 h275.59
  text "PA0" at 269.45,2374.02 h78.74
  text "PC10" at 2052.29,2366.54 h78.74
  text "PA1" at 269.45,2274.02 h78.74
  text "PA15" at 2053.33,2266.54 h78.74
  text "C" at 1179.13,2236.22 h275.59
  text "H" at 1541.34,2226.38 h275.59
  text "PA2" at 269.45,2174.02 h78.74
  text "PA14" at 2054.75,2166.54 h78.74
  text "PA3" at 269.45,2074.02 h78.74
  text "VDDIO2" at 2110.27,2066.54 h78.74
  text "VDDA" at 2071.4,1966.54 h78.74
  text "GND" at 264.33,1964.57 h78.74
  text "VDD" at 264.33,1866.14 h78.74
  text "PA13" at 2053.22,1866.54 h78.74
  text "PA4" at 269.45,1774.02 h78.74
  text "PA12" at 2053.44,1766.54 h78.74
  text "PA5" at 269.45,1674.02 h78.74
  text "PA11" at 2053.54,1666.54 h78.74
  text "PA6" at 269.45,1574.02 h78.74
  text "PA10" at 2054.47,1566.54 h78.74
  text "PA7" at 269.45,1474.02 h78.74
  text "PA9" at 2029.14,1466.54 h78.74
  text "PC4" at 269.45,1374.02 h78.74
  text "PA8" at 2029.63,1366.54 h78.74
  text "PC5" at 269.45,1274.02 h78.74
  text "PC9" at 2026.95,1266.54 h78.74
  text "PB0" at 269.45,1174.02 h78.74
  text "PC8" at 2027.45,1166.54 h78.74
  text "PB1" at 269.45,1074.02 h78.74
  text "PC7" at 2027.23,1066.54 h78.74
  text "PB2" at 269.45,974.02 h78.74
  text "PC6" at 2027.5,966.54 h78.74
  text "PB10" at 269.45,874.02 h78.74
  text "PB15" at 2051.63,866.54 h78.74
  text "PB11" at 269.45,774.02 h78.74
  text "PB14" at 2053.05,766.54 h78.74
  text "PB12" at 269.45,674.02 h78.74
  text "PB13" at 2051.52,666.54 h78.74
  text "GND" at 269.45,574.02 h78.74
  text "GND" at 2045.3,566.54 h78.74
  text "SILKSCREEN BOTTOM LAYER" at -986.61,-3501.57 h96.46
Top Paste:
  text "PASTE MASK TOP LAYER" at -986.61,-3501.57 h96.46
Bottom Paste:
  text "PASTE MASK BOTTOM LAYER" at -986.61,-3501.57 h96.46
Top Mask:
  text "SOLDER MASK TOP LAYER" at -986.61,-3501.57 h96.46
Bottom Solder:
  text "SOLDER MASK BOTTOM LAYER" at -986.61,-3501.57 h96.46
PLEXI:
  lines w8: 56.69,2004.33 ccw(c115.75,2004.33) 115.75,1945.28 2084.25,1945.28 ccw(c2084.25,2004.33) 2143.31,2004.33 2143.31,2398.03 ccw(c2084.25,2398.03) 2084.25,2457.09 115.75,2457.09 ccw(c115.75,2398.03) 56.69,2398.03 56.69,2004.33 ; 765.35,986.61 cw(c765.35,1498.43) 765.35,2010.24 cw(c765.35,1498.43) 765.35,986.61 ; 1139.37,1183.46 cw(c1139.37,1203.15) 1139.37,1222.83 cw(c1139.37,1203.15) 1139.37,1183.46 ; 1277.17,1281.89 cw(c1277.17,1340.94) 1277.17,1400 cw(c1277.17,1340.94) 1277.17,1281.89 ; 1336.22,1124.41 cw(c1336.22,1380.32) 1336.22,1636.22 cw(c1336.22,1380.32) 1336.22,1124.41
  text "Plaque acrylique 1,5mm incolore." at 155.12,1197.75 h45.94
  text "pose double face 3M 200P" at 155.12,1124.41 h45.94
MECHANICAL DRAWING:
  text "MECHANICAL DRAWING" at -986.61,-3501.57 h96.46
Top Assy:
  text "ASSEMBLY TOP LAYER" at -986.61,-3501.57 h96.46
Top ZI:
  lines w8: -125,3850 -125,4450 675,4450 675,3850 -125,3850
Bot Assy:
  text "ASSEMBLY BOTTOM LAYER" at 3147.24,-3501.57 h96.46
User Attributes:
  lines w10: 725,655 1075,655 ; 827.51,407.51 1075,655 ; 827.51,902.49 1075,655 ; 1322.49,407.51 1075,655 ; 1322.49,902.49 1075,655 ; 1425,655 1075,655 ; 1075,305 cw(c1075,655) 1075,1005 ; 1075,305 ccw(c1075,655) 1075,1005 ; 1075,305 1075,655 ; 1075,655 1075,1005 ; 1075,455 cw(c1075,655) 1075,855 cw(c1075,655) 1075,455
PERCAGES:
  text "DRILL DRAWING" at -986.61,-3501.57 h96.46
CARTOUCHE F1:
  region: 3800,-4050 4029.54,-4049.9 4040,-4029 3950,-3939 3938,-3912 3938,-3879 3941,-3867 3953,-3846 3965,-3834 3980,-3825 3998,-3819 4019,-3816 4445,-3816 4421,-3879 4418,-3882 4319,-3882 4223,-4110 4154,-4110 4247,-3891 4247,-3882 4010,-3882 4004,-3885 4001,-3891 4001,-3900 4004,-3903 4091,-3987 4100,-4002 4103,-4017 4106,-4020 4106,-4047 cw(c4016.51,-4028.61) 4058,-4110 3776,-4110 3776,-4104 3797,-4053
  lines w8: -1037.53,-4421.08 3262.47,-4421.08 ; -1037.53,-4071.08 3262.47,-4071.08 ; 3776,-4110 3782,-4116 4277,-4116 ccw(c4254.75,-4019) 4343,-4065 4463,-3777 4463,-3765 4460,-3762 3962,-3762 ccw(c3981.43,-3855.35) 3896,-3813 3776,-4104 3776,-4110
  lines w20: -2487.53,-4721.08 -2487.53,-3121.08 5012.47,-3121.08 ; -2387.53,-4121.08 -1187.53,-4121.08 ; -2387.53,-3671.08 -1187.53,-3671.08 ; -2861.54,-4721.08 -2861.54,6578.13 5012.47,6578.13 5012.47,-4721.08 -2861.54,-4721.08 ; -2387.53,-4621.08 -1187.53,-4621.08 -1187.53,-3221.08 -2387.53,-3221.08 -2387.53,-4621.08 ; -1087.53,-4621.08 -1087.53,-3721.08 3312.47,-3721.08 3312.47,-4621.08 -1087.53,-4621.08 ; -1087.53,-3621.08 3312.47,-3621.08 3312.47,-3221.08 -1087.53,-3221.08 -1087.53,-3621.08 ; 3412.47,-4621.08 4912.47,-4621.08 4912.47,-3221.08 3412.47,-3221.08 3412.47,-4621.08
  text "DATE:" at -2352,-3514.91 h70
  text "07/10/2013" at -2315,-3650 h70
  text "STM32F072B-DISCOVERY" at -991.47,-4032.1 h96.46
  text "MB1076C" at -991.47,-4386.43 h96.46
  text "S.M.E.E." at -2250,-4500 h165.35
Drill Drawing:
  drawing of 206 lines, arcs and shapes, not listed
  text "Symbol" at -2762.39,6344.72 h118.11
  text "Hit Count" at -2324.19,6344.72 h118.11
  text "Finished Hole Size" at -1795.16,6344.72 h118.11
  text "Plated" at -828.71,6344.72 h118.11
  text "Drill Layer Pair" at -447.02,6344.72 h118.11
  text "F" at 399.49,6318.72 h75
  text "F" at 399.49,6318.72 h75
  text "IMPEDANCE TABLE" at 589.49,6308.72 h85
  text "266" at -2324.19,6181.65 h98.43
  text "0.30mm" at -1795.16,6181.65 h98.43
  text "PTH" at -828.71,6181.65 h98.43
  text "TOP - Bottom" at -447.02,6181.65 h98.43
  text "LAYER" at 599.49,6038.72 h75
  text "TOLERANCE" at 4349.49,6038.72 h75
  text "TRACE" at 1349.49,6028.72 h75
  text "SPACEING" at 1899.49,6028.72 h75
  text "IMPEDANCE" at 2649.49,6028.72 h75
  text "IMPEDANCE" at 3549.49,6028.72 h75
  text "4" at -2324.19,6018.58 h98.43
  text "0.70mm" at -1795.16,6018.58 h98.43
  text "PTH" at -828.71,6018.58 h98.43
  text "TOP - Bottom" at -447.02,6018.58 h98.43
  text "(mil)" at 1399.49,5938.72 h50
  text "(Single end)" at 2699.49,5938.72 h50
  text "(mil)" at 1999.49,5928.72 h50
  text "(Differential)" at 3549.49,5928.72 h50
  text "6" at -2324.19,5855.52 h98.43
  text "0.90mm" at -1795.16,5855.52 h98.43
  text "PTH" at -828.71,5855.52 h98.43
  text "TOP - Bottom" at -447.02,5855.52 h98.43
  text "N/A" at 2049.49,5738.72 h75
  text "N/A" at 3699.49,5738.72 h75
  text "+/-10%" at 4449.49,5738.72 h75
  text "N/A" at 2799.49,5724.94 h75
  text "N/A" at 1374.49,5716.74 h75
  text "N/A" at 659.49,5703.72 h75
  text "4" at -2324.19,5692.45 h98.43
  text "1.00mm" at -1795.16,5692.45 h98.43
  text "NPTH" at -828.71,5692.45 h98.43
  text "TOP - Bottom" at -447.02,5692.45 h98.43
  text "76" at -2324.19,5529.38 h98.43
  text "1.00mm" at -1795.16,5529.38 h98.43
  text "PTH" at -828.71,5529.38 h98.43
  text "TOP - Bottom" at -447.02,5529.38 h98.43
  text "1,2" at 549.49,5488.72 h75
  text "6.55" at 1399.49,5488.72 h75
  text "6.45" at 2049.49,5488.72 h75
  text "N/A" at 2799.49,5488.72 h75
  text "90 OHM" at 3599.49,5488.72 h75
  text "+/-10%" at 4449.49,5488.72 h75
  text "2" at -2324.19,5366.31 h98.43
  text "1.20mm" at -1795.16,5366.31 h98.43
  text "NPTH" at -828.71,5366.31 h98.43
  text "TOP - Bottom" at -447.02,5366.31 h98.43
  text "358 Total" at -2324.19,5203.24 h98.43
  text "silkscreen color为White，soldermask  color为blue" at -1860.24,-925.2 h160
  text "Layer" at -2394.47,-1349.59 h100
  text "Name" at -1975.98,-1349.59 h100
  text "Material" at -1166.69,-1349.59 h100
  text "Thickness" at -439.44,-1349.59 h100
  text "Constant" at 157.94,-1349.59 h100
  text "Board Layer Stack" at 710.83,-1349.59 h100
  text "1" at -2394.47,-1549.59 h100
  text "Top Silk" at -1975.98,-1549.59 h100
  text "2" at -2394.47,-1749.59 h100
  text "Top Mask" at -1975.98,-1749.59 h100
  text "Solder Resist" at -1166.69,-1749.59 h100
  text "0.010mm" at -439.44,-1749.59 h100
  text "3.5" at 157.94,-1749.59 h100
  text "3" at -2394.47,-1949.59 h100
  text "TOP" at -1975.98,-1949.59 h100
  text "Copper" at -1166.69,-1949.59 h100
  text "0.035mm" at -439.44,-1949.59 h100
  text "Cu + Plated" at 129.92,-1956.69 h100
  text "4" at -2394.47,-2149.59 h100
  text "Dielectric 1" at -1975.98,-2149.59 h100
  text "FR-4" at -1166.69,-2149.59 h100
  text "1.465mm" at -439.44,-2149.59 h100
  text "4.8" at 157.94,-2149.59 h100
  text "5" at -2394.47,-2349.59 h100
  text "Bottom" at -1975.98,-2349.59 h100
  text "Copper" at -1166.69,-2349.59 h100
  text "0.035mm" at -439.44,-2349.59 h100
  text "Cu + Plated" at 131.89,-2350.39 h100
  text "6" at -2394.47,-2549.59 h100
  text "Bottom Solder" at -1975.98,-2549.59 h100
  text "Solder Resist" at -1166.69,-2549.59 h100
  text "0.010mm" at -439.44,-2549.59 h100
  text "3.5" at 157.94,-2549.59 h100
  text "7" at -2394.47,-2749.59 h100
  text "Bottom Overlay" at -1975.98,-2749.59 h100
CARTOUCHE FX:
  region: -1648.16,-4050.97 -1877.7,-4050.87 -1888.16,-4029.97 -1798.16,-3939.97 -1786.16,-3912.97 -1786.16,-3879.97 -1789.16,-3867.97 -1801.16,-3846.97 -1813.16,-3834.97 -1828.16,-3825.97 -1846.16,-3819.97 -1867.16,-3816.97 -2293.16,-3816.97 -2269.16,-3879.97 -2266.16,-3882.97 -2167.16,-3882.97 -2071.16,-4110.97 -2002.16,-4110.97 -2095.16,-3891.97 -2095.16,-3882.97 -1858.16,-3882.97 -1852.16,-3885.97 -1849.16,-3891.97 -1849.16,-3900.97 -1852.16,-3903.97 -1939.16,-3987.97 -1948.16,-4002.97 -1951.16,-4017.97 -1954.16,-4020.97 -1954.16,-4047.97 ccw(c-1864.67,-4029.58) -1906.16,-4110.97 -1624.16,-4110.97 -1624.16,-4104.97 -1645.16,-4053.97
  lines w8: -1110.63,-4422.05 3189.37,-4422.05 ; -1110.63,-4072.05 3189.37,-4072.05 ; -2311.16,-3777.97 -2311.16,-3765.97 -2308.16,-3762.97 -1810.16,-3762.97 cw(c-1829.59,-3856.32) -1744.16,-3813.97 -1624.16,-4104.97 -1624.16,-4110.97 -1630.16,-4116.97 -2125.16,-4116.97 cw(c-2102.91,-4019.97) -2191.16,-4065.97 -2311.16,-3777.97
  lines w20: -2860.63,-3122.05 4639.37,-3122.05 4639.37,-4722.05 ; 3339.37,-4122.05 4539.37,-4122.05 ; 3339.37,-3672.05 4539.37,-3672.05 ; -2860.63,-4722.05 -2860.63,6577.16 5013.39,6577.16 5013.39,-4722.05 -2860.63,-4722.05 ; -2760.63,-4622.05 -2760.63,-3222.05 -1260.63,-3222.05 -1260.63,-4622.05 -2760.63,-4622.05 ; -1160.63,-4622.05 3239.37,-4622.05 3239.37,-3722.05 -1160.63,-3722.05 -1160.63,-4622.05 ; -1160.63,-3622.05 3239.37,-3622.05 3239.37,-3222.05 -1160.63,-3222.05 -1160.63,-3622.05 ; 3339.37,-4622.05 4539.37,-4622.05 4539.37,-3222.05 3339.37,-3222.05 3339.37,-4622.05
  text "DATE:" at 4477.04,-3423.8 h70
  text "07/10/2013" at 4477.04,-3581.28 h70
  text "STM32F052B-DISCOVERY" at 3143.31,-4033.07 h96.46
  text "MB1076C" at 3143.31,-4387.4 h96.46
  text "S.M.E.E." at 4401.84,-4500.97 h165.35

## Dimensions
2200,0 to 2200,4400 on Drill Drawing
0,0 to 2200,0 on Drill Drawing
2200,0 to 2200,4400 on MECHANICAL DRAWING
0,0 to 2200,0 on MECHANICAL DRAWING
0,0 to 350,600 on MECHANICAL DRAWING
350,3800 to 0,4400 on PERCAGES
0,4400 to 0,0 on PERCAGES
1850,3800 to 2200,4400 on PERCAGES
350,600 to 1850,600 on MECHANICAL DRAWING
350,3800 to 0,4400 on PERCAGES
550,3600 to 350,3800 on MECHANICAL DRAWING
0,4400 to 2200,4400 on PERCAGES
350,600 to 0,0 on PERCAGES
115.75,2457.09 to 115.75,1945.28 on PLEXI
56.69,2398.03 to 2143.31,2398.03 on PLEXI
0,4400 to 2200,4400 on MECHANICAL DRAWING
1850,3800 to 2200,4400 on MECHANICAL DRAWING
1850,3800 to 1850,600 on MECHANICAL DRAWING
350,3800 to 0,4400 on MECHANICAL DRAWING
350,600 to 0,0 on MECHANICAL DRAWING
350,3800 to 1850,3800 on MECHANICAL DRAWING
350,3800 to 350,600 on MECHANICAL DRAWING
0,0 to 0,4400 on MECHANICAL DRAWING
550,3600 to 350,3800 on MECHANICAL DRAWING
1850,600 to 2200,0 on MECHANICAL DRAWING
1850,3800 to 2200,4400 on MECHANICAL DRAWING
1850,600 to 2200,0 on MECHANICAL DRAWING
350,3800 to 0,4400 on MECHANICAL DRAWING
